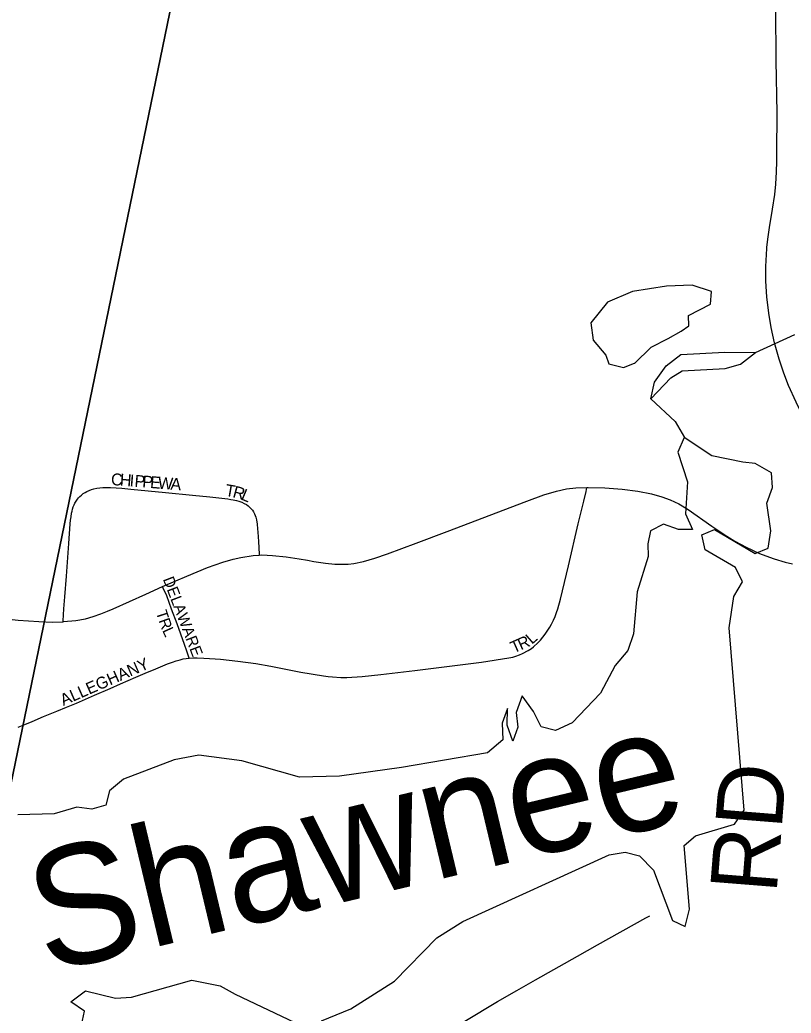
# Model space of a CAD drawing. Extents: x -13.9 to 69.1, y -25.2 to 26.1.
# Drawn here: x 2.268 to 2.853, y 17.221 to 17.974 of the extents above; entities that cross this region are included whole.
import ezdxf

# ---------------------------------------------------------------- set-up
doc = ezdxf.new("R2010")
doc.units = 0
for name, color, linetype in [('GM_X_County_Road', 7, 'Continuous'), ('GM_X_County_Road_Text', 7, 'Continuous'), ('GM_X_Major_Lake', 7, 'Continuous'), ('GM_X_Major_Lake_Text', 7, 'Continuous'), ('GM_X_Major_River', 7, 'Continuous'), ('GM_X_Minor_Lake', 7, 'Continuous'), ('GM_X_Township', 7, 'Continuous'), ('GM_X_Township_Road', 7, 'Continuous'), ('GM_X_Township_Subdivision', 7, 'Continuous'), ('GM_X_Township_Subdivision_Text', 7, 'Continuous')]:
    doc.layers.add(name, color=color, linetype=linetype)

msp = doc.modelspace()

# ---------------------------------------------------------------- linework, layer by layer
at = {"layer": 'GM_X_County_Road'}
for points in [[(2.84181, 17.94359), (2.84168, 17.95185), (2.84117, 17.99764)], [(2.83469, 17.80174), (2.83545, 17.80798), (2.83666, 17.81676), (2.83912, 17.83077), (2.84069, 17.84197), (2.8415, 17.84968), (2.8421, 17.8592), (2.84234, 17.86694), (2.84232, 17.87347), (2.84242, 17.90369), (2.84181, 17.94359)], [(2.89206, 17.60829), (2.8912, 17.61201), (2.88938, 17.61715), (2.8853, 17.62569), (2.87921, 17.63838), (2.86864, 17.65995), (2.85691, 17.68421), (2.85118, 17.69703), (2.84752, 17.70627), (2.844, 17.71684), (2.84055, 17.72933), (2.83802, 17.74086), (2.83618, 17.75193), (2.83478, 17.76429), (2.834, 17.7761), (2.83391, 17.78734), (2.8346, 17.80095), (2.83469, 17.80174)]]:
    msp.add_lwpolyline(points, dxfattribs=at)
at = {"layer": 'GM_X_Major_Lake'}
for points in [[(2.80618, 17.51289), (2.80971, 17.53678), (2.81635, 17.54788), (2.81084, 17.55891), (2.78785, 17.57216), (2.78539, 17.58348), (2.79492, 17.58762), (2.8259, 17.56945), (2.83577, 17.57358), (2.83773, 17.58661), (2.83479, 17.60774), (2.83908, 17.61962), (2.8383, 17.63054), (2.82597, 17.63773), (2.81654, 17.63868), (2.79304, 17.64359), (2.77208, 17.65753), (2.76713, 17.64639), (2.77441, 17.62369), (2.7729, 17.5994), (2.77839, 17.58764), (2.76759, 17.58753), (2.75622, 17.5918), (2.74633, 17.58659), (2.74444, 17.57682), (2.74457, 17.56701), (2.73626, 17.54033), (2.73358, 17.50843), (2.72927, 17.49582), (2.71959, 17.48443), (2.70836, 17.46327), (2.68699, 17.44089), (2.67439, 17.43501), (2.66331, 17.43782), (2.65749, 17.44958), (2.64896, 17.4614), (2.64432, 17.4488), (2.64577, 17.4375), (2.64184, 17.42706), (2.63771, 17.43915), (2.63797, 17.45185), (2.63369, 17.4407), (2.63444, 17.42797), (2.62277, 17.41807), (2.55745, 17.40691), (2.51043, 17.40039), (2.48006, 17.39965), (2.43614, 17.41195), (2.40351, 17.41635), (2.38489, 17.4128), (2.34648, 17.39809), (2.33584, 17.38926), (2.33292, 17.37843), (2.3224, 17.37541), (2.31096, 17.37677), (2.29366, 17.37173), (2.26632, 17.37093)], [(2.49681, 17.21475), (2.51891, 17.22367), (2.55206, 17.24468), (2.58411, 17.2777), (2.60393, 17.28995), (2.71493, 17.34071), (2.72711, 17.3426), (2.73818, 17.3398), (2.74875, 17.32902), (2.76313, 17.29091), (2.77282, 17.28632), (2.77612, 17.29932), (2.77207, 17.34772), (2.78065, 17.35514), (2.81017, 17.36389), (2.81748, 17.37461), (2.80618, 17.51289)], [(2.31462, 17.21143), (2.31686, 17.22191), (2.30655, 17.22905), (2.31752, 17.23751), (2.34033, 17.23189), (2.35249, 17.23269), (2.39829, 17.24541), (2.41978, 17.24127), (2.43112, 17.23483), (2.47654, 17.21342)]]:
    msp.add_lwpolyline(points, dxfattribs=at)
at = {"layer": 'GM_X_Major_River'}
for points in [[(2.82603, 17.72199), (2.85583, 17.73561)], [(2.74672, 17.68682), (2.74934, 17.69947), (2.75837, 17.71197), (2.76934, 17.72043), (2.80276, 17.72218), (2.82603, 17.72199)], [(2.74672, 17.68682), (2.76189, 17.70281), (2.77043, 17.70805), (2.80318, 17.70982), (2.81472, 17.71318), (2.82603, 17.72199)], [(2.74672, 17.68682), (2.76525, 17.66967), (2.77212, 17.6575)]]:
    msp.add_lwpolyline(points, dxfattribs=at)
at = {"layer": 'GM_X_Minor_Lake'}
for points in [[(2.747, 17.72593), (2.75991, 17.73262), (2.76978, 17.73827), (2.77556, 17.74218), (2.77534, 17.75017), (2.79199, 17.75862), (2.7928, 17.76842), (2.77803, 17.77302), (2.75845, 17.77225), (2.73276, 17.76831), (2.71375, 17.76026), (2.70105, 17.74448), (2.70288, 17.73137), (2.7125, 17.71995), (2.71477, 17.71338), (2.72587, 17.71065), (2.73434, 17.71379)], [(2.73422, 17.71374), (2.747, 17.72593)]]:
    msp.add_lwpolyline(points, dxfattribs=at)
at = {"layer": 'GM_X_Township'}
for points in [[(2.20226, 16.14501), (2.21595, 16.45704), (2.17111, 16.462), (2.17937, 16.53249), (2.23038, 17.24665), (2.57136, 18.90232), (2.59954, 20.01177)], [(7.86611, 18.45895), (4.52881, 18.78157), (2.57136, 18.90232), (2.23038, 17.24665), (2.17937, 16.53249), (2.17111, 16.462), (2.21595, 16.45704), (2.20226, 16.14501)]]:
    msp.add_lwpolyline(points, dxfattribs=at)
at = {"layer": 'GM_X_Township_Road'}
for points in [[(2.4495, 17.56816), (2.45132, 17.56829), (2.45947, 17.56794), (2.46987, 17.56693), (2.47961, 17.56537), (2.48608, 17.56423), (2.49095, 17.56344), (2.49968, 17.56207), (2.50684, 17.56139), (2.51297, 17.56128), (2.51681, 17.56144), (2.52122, 17.56192), (2.52862, 17.56338), (2.5372, 17.56576), (2.54666, 17.56906), (2.56862, 17.57722), (2.59209, 17.586), (2.65246, 17.60924), (2.66553, 17.61395), (2.67506, 17.61684), (2.68257, 17.61845), (2.68964, 17.61928), (2.69816, 17.61951)], [(2.69816, 17.61951), (2.69897, 17.61954), (2.71164, 17.61922), (2.72483, 17.61822), (2.73686, 17.61663), (2.74714, 17.61465), (2.75513, 17.61251), (2.76132, 17.61022), (2.76779, 17.60706), (2.77495, 17.60271), (2.79304, 17.59022), (2.80424, 17.5825), (2.8105, 17.57865), (2.81896, 17.57412), (2.8292, 17.56951), (2.83389, 17.56767), (2.8402, 17.56543), (2.84874, 17.56283), (2.85417, 17.56164)], [(2.37605, 17.54427), (2.38622, 17.54877), (2.39437, 17.55226), (2.41021, 17.55882), (2.42168, 17.56292), (2.42964, 17.56512), (2.43555, 17.5664), (2.44479, 17.56781), (2.4495, 17.56816)], [(2.30049, 17.51766), (2.30088, 17.51767), (2.3103, 17.51862), (2.31744, 17.51989), (2.3234, 17.52148), (2.32921, 17.52355), (2.33434, 17.52572), (2.33844, 17.52746), (2.36333, 17.53865), (2.37605, 17.54427)], [(2.25728, 17.51985), (2.26657, 17.51889), (2.28202, 17.51767), (2.29256, 17.5174), (2.30049, 17.51766)]]:
    msp.add_lwpolyline(points, dxfattribs=at)
at = {"layer": 'GM_X_Township_Subdivision'}
for points in [[(2.30049, 17.51766), (2.30055, 17.51836), (2.30122, 17.52734), (2.3019, 17.53643), (2.30308, 17.5521), (2.30419, 17.56646), (2.30497, 17.57697), (2.30604, 17.59186), (2.30626, 17.59474), (2.3066, 17.59726), (2.30702, 17.59991), (2.30734, 17.60156), (2.30769, 17.6031), (2.30832, 17.60488), (2.309, 17.60642), (2.30959, 17.6076), (2.31049, 17.60918), (2.31138, 17.61059), (2.31214, 17.61158), (2.31331, 17.61271), (2.31454, 17.61379), (2.31591, 17.61486), (2.31731, 17.61577), (2.31865, 17.6165), (2.32031, 17.61725), (2.32203, 17.61791), (2.324, 17.61846), (2.32625, 17.61901), (2.32836, 17.61926), (2.3307, 17.61945), (2.33331, 17.61955), (2.33642, 17.61948), (2.34093, 17.61926), (2.3452, 17.61895), (2.35201, 17.61828), (2.37838, 17.61568), (2.3987, 17.61377), (2.41188, 17.61251), (2.42557, 17.6109), (2.42776, 17.61053), (2.42963, 17.61016), (2.4321, 17.60962), (2.43403, 17.60912), (2.4362, 17.60838), (2.43808, 17.60746), (2.43974, 17.60654), (2.441, 17.60562), (2.44213, 17.60464), (2.4431, 17.60366), (2.44431, 17.6023), (2.44519, 17.60094), (2.4459, 17.59954), (2.44639, 17.59833), (2.44677, 17.59689), (2.44729, 17.59494), (2.44779, 17.59167), (2.44817, 17.58811), (2.44839, 17.58557), (2.44886, 17.57851), (2.44945, 17.569), (2.4495, 17.56816)], [(2.39615, 17.49006), (2.39896, 17.49028), (2.40229, 17.4903), (2.40727, 17.49004), (2.4117, 17.48976), (2.41589, 17.48941), (2.41997, 17.48908), (2.43308, 17.48762), (2.44677, 17.48587), (2.4582, 17.48379), (2.48092, 17.47936), (2.49833, 17.47651), (2.50184, 17.47604), (2.50505, 17.47579), (2.51141, 17.47541), (2.51602, 17.47537), (2.52756, 17.47595), (2.54183, 17.47745), (2.56763, 17.48069), (2.60003, 17.4846), (2.61816, 17.48685), (2.63888, 17.49012), (2.64181, 17.49075), (2.64416, 17.49147), (2.64685, 17.4924), (2.64928, 17.4934), (2.65363, 17.49574), (2.65599, 17.49736), (2.65765, 17.49865), (2.66097, 17.50163), (2.66287, 17.50366), (2.66471, 17.50582), (2.66645, 17.50806), (2.66807, 17.5104), (2.66996, 17.51341), (2.67125, 17.51585), (2.67274, 17.51876), (2.67399, 17.52149), (2.67515, 17.52474), (2.67607, 17.52749), (2.678, 17.53473), (2.67969, 17.54118), (2.68429, 17.56007), (2.69153, 17.59184), (2.69569, 17.60917), (2.69745, 17.61656), (2.69816, 17.61951)], [(2.39615, 17.49006), (2.39595, 17.49069), (2.39446, 17.49526), (2.39272, 17.50044), (2.38703, 17.51603), (2.38295, 17.52708), (2.37918, 17.53731), (2.37659, 17.54307), (2.37605, 17.54427)], [(2.26645, 17.43749), (2.27029, 17.43914), (2.27697, 17.44201), (2.28559, 17.44572), (2.29576, 17.44982), (2.30312, 17.45282), (2.31066, 17.4559), (2.32444, 17.4618), (2.33632, 17.467), (2.34423, 17.47057), (2.35585, 17.47561), (2.36294, 17.47853), (2.37102, 17.48186), (2.37991, 17.4856), (2.38362, 17.487), (2.38633, 17.48794), (2.38934, 17.48882), (2.39172, 17.48944), (2.39392, 17.48981), (2.39615, 17.49006)], [(2.6054, 17.21432), (2.6304, 17.22925), (2.64501, 17.23765), (2.65916, 17.2457), (2.6909, 17.26375), (2.70608, 17.27231), (2.74292, 17.29275), (2.74587, 17.29435)]]:
    msp.add_lwpolyline(points, dxfattribs=at)

# ---------------------------------------------------------------- texts
at = {"layer": 'GM_X_County_Road_Text'}
msp.add_text('RD', height=0.050575, rotation=85.45784, dxfattribs=at).set_placement((2.84201, 17.31068))
at = {"layer": 'GM_X_Major_Lake_Text'}
msp.add_text('Shawnee', height=0.090342, rotation=13.43374, dxfattribs=at).set_placement((2.28746, 17.25068))
at = {"layer": 'GM_X_Township_Subdivision_Text'}
for s, height, rotation, p in [('C', 0.00906, 357.72676, (2.33682, 17.62125)), ('H', 0.00906, 355.69416, (2.34342, 17.62099)), ('I', 0.00906, 355.3878, (2.3508, 17.62043)), ('P', 0.00906, 355.41239, (2.3545, 17.62013)), ('P', 0.00906, 355.41239, (2.36041, 17.61966)), ('E', 0.00906, 355.41239, (2.36633, 17.61918)), ('W', 0.00906, 355.41667, (2.37224, 17.61871)), ('A', 0.00906, 355.41123, (2.38185, 17.61794)), ('T', 0.00905, 350.30078, (2.42309, 17.61325)), ('R', 0.00903, 344.68137, (2.42875, 17.6123)), ('L', 0.00898, 337.26533, (2.43495, 17.61062)), ('DELAWARE', 0.008519, 290.90195, (2.37619, 17.54996)), ('T', 0.0085, 288.21594, (2.37084, 17.52484)), ('R', 0.00851, 289.67576, (2.37291, 17.51857)), ('L', 0.00855, 294.56248, (2.37563, 17.51107)), ('L', 0.00882, 40.89132, (2.65637, 17.50007)), ('T', 0.00897, 23.84587, (2.64248, 17.49349)), ('R', 0.00897, 23.87152, (2.64797, 17.49592)), ('ALLEGHANY', 0.008975, 23.66868, (2.30073, 17.45362))]:
    msp.add_text(s, height=height, rotation=rotation, dxfattribs=at).set_placement(p)

doc.saveas('drawing.dxf')
